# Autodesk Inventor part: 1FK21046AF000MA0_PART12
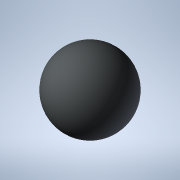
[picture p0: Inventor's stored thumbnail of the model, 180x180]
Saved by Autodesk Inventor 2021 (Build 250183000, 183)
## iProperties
Created: 2025-04
Part Number: 1FK21046AF000MA0_PART12
Material: Generic
Catalog Web Link: www.3dfindit.com
Description: -Servo synchronous motor
Document SubType Name: Modeling
Designer: psAdmin
Mass: 0.137258 g
Surface Area: 1.2868 cm^2
Volume: 0.137258 cm^3
Density: 1 g/cm^3
Appearance: PSOLRGB-212-217-219
Category: PARTsolutions
Title: 1FK21046AF000MA0_PART12
Author: Cadenas PARTsolutions
Comments: Servo synchronous motor
Sending System: PARTsolutions
Preprocessor: ST-DEVELOPER v19.3
PSOL_IDENT_0: {$CADENAS_DATA/23d-libs/siemens_ag/_cat_/1c/1f/1fk21046af000ma0.prj},216 {VTYP=3D},{NB=1FK21046AF000
PSOL_IDENT_1: MA0_PART12},{LINA=1FK21046AF000MA0_PART12},{NN=1FK21046AF000MA0_PART12},{NOPRJ=TRUE},{DATE=19.08.202
PSOL_IDENT_2: 5 14:00:28},{GEOMDATE=30.07.2025 02:02:08},{VERSION=},{LINEID=10},{WBVAR=},{WBNUMERIC=}  {NB=1FK2104
PSOL_IDENT_3: 6AF000MA0_PART12},{LINA=1FK21046AF000MA0_PART12},{KT=DUMMY},{PREVIEW=../../../_pool_/cb/72/p_d211_xx
PSOL_IDENT_4: _00434j.png},{DESCSHORT=SIMOTICS S-1FK2 HD, SINAMICS S210 3AC 400V-480V, 3.2 Nm, 3000 rpm},{DESCLONG=
PSOL_IDENT_5: SIMOTICS S-1FK2 HD servo motor M0=3.2 Nm; PN = 1 kW at nN=3000 rpm (380-480 V); PN = 0.5 kW at nN=15
PSOL_IDENT_6: 00 rpm (200-240 V); degree of protection IP64; cylindrical shaft D19x40mm; absolute encoder 22-bit +
PSOL_IDENT_7: 12-bit multiturn (encoder AM22DQC); with OCC interface; plug size M17, rotatable; SIMOTICS S-1FK2 s
PSOL_IDENT_8: ervomotorfor a wide range of uses in industrial environments. SIMOTICS S‑1FK2 servomotors are compac
PSOL_IDENT_9: t synchronous motors with a high dynamic performance that set themselves apart as a result of their
PSOL_IDENT_10: high power density, degree of protection and overload capability. The motors are available in two va
PSOL_IDENT_11: riants: as High Dynamic variant (highest dynamic performance as a result of the low intrinsic moment
PSOL_IDENT_12: of inertia for applications demanding a high dynamic performance with low moved masses) - and as Co
PSOL_IDENT_13: mpact variant (precise and stable closed-loop control for medium up to large moved masses as a resul
PSOL_IDENT_14: t of a medium intrinsic moment of inertia). SIMOTICSS‑1FK2 servomotors fully exploit their strengths
PSOL_IDENT_15: in a system with the SINAMICSS210 frequency converter and simple connection using the one cable con
PSOL_IDENT_16: nection (OCC). Advantages include the short control and positioning times, fast and precise correcti
PSOL_IDENT_17: on of disturbing quantities as well as stable control with a high dynamic performance. The servo mot
PSOL_IDENT_18: ors can be configured to address a wide range of requirements. For example with and without holding
PSOL_IDENT_19: brake, IP64 or IP65 degree of protection, singleturn or multiturn absolute encoders - to name just a
PSOL_IDENT_20: few. Further, the servomotors are available in different shaft heights extending from 20 to 100. A
PSOL_IDENT_21: shaft sealing ring is available to achieve an IP65 degree of protection and for subsequent mounting
PSOL_IDENT_22: at the motor or as spare part. SIMOTICS - the optimum motor for each and every motion control applic
PSOL_IDENT_23: ation.},{INTNO=195125049666},{SUPPLIERALTNO=1FK2104-6AF00-0MA0},{MANUID=1FK21046AF000MA0},{MANUNAME=
PSOL_IDENT_24: Siemens},{MANUTYPEDESC=Synchronous motor 1FK2-HD 3.2 NM},{AAU732=SIMOTICS},{AAO057=S-1FK2},{AAU734=S
PSOL_IDENT_25: IMOTICS S-1FK2 HD servo motor M0=3.2 Nm; PN = 1 kW at nN=3000 rpm (380-480 V); PN = 0.5 kW at nN=150
PSOL_IDENT_26: 0 rpm (200-240 V); degree of protection IP64; cylindrical shaft D19x40mm; absolute encoder 22-bit +
PSOL_IDENT_27: 12-bit multiturn (encoder AM22DQC); with OCC interface; plug size M17, rotatable;},{AAW338=Synchrono
PSOL_IDENT_28: us motor 1FK2-HD 3.2 NM},{AAO742=SIMOTICS},{AAO663=4042948694374},{NOCUPEROU=1},{PRICEQUANTITY=1},{Q
PSOL_IDENT_29: UANTITYMIN=1},{QUANTITYINT=1},{CTN=85015220},{COO=DE},{AAO676=1FK2104-6AF00-0MA0},{AAO677=Siemens AG
PSOL_IDENT_30: },{ORDERUNIT=C62},{CONTENTUNIT=C62}
NB: 1FK21046AF000MA0_PART12
NT: Servo synchronous motor
NBSYN: $MANUID._PART12
LINA: 1FK21046AF000MA0_PART12
CATALOG: SIEMENS
PREVIEW: ../../../_pool_/cb/72/p_d211_xx_00434j.png
DESCSHORT: SIMOTICS S-1FK2 HD, SINAMICS S210 3AC 400V-480V, 3.2 Nm, 3000 rpm
DESCLONG: SIMOTICS S-1FK2 HD servo motor M0=3.2 Nm; PN = 1 kW at nN=3000 rpm (380-480 V); PN = 0.5 kW at nN=1500 rpm (200-240 V); degree of protection IP64; cylindrical s
INTNO: 195125049666
SUPPLIERALTNO: 1FK2104-6AF00-0MA0
MANUID: 1FK21046AF000MA0
MANUNAME: Siemens
MANUTYPEDESC: Synchronous motor 1FK2-HD 3.2 NM
AAU732: SIMOTICS
AAO057: S-1FK2
AAU734: SIMOTICS S-1FK2 HD servo motor M0=3.2 Nm; PN = 1 kW at nN=3000 rpm (380-480 V); PN = 0.5 kW at nN=1500 rpm (200-240 V); degree of protection IP64; cylindrical s
AAW338: Synchronous motor 1FK2-HD 3.2 NM
AAO742: SIMOTICS
AAO663: 4042948694374.0
NOCUPEROU: 1
PRICEQUANTITY: 1
QUANTITYMIN: 1
QUANTITYINT: 1
CTN: 85015220
COO: DE
ARTICLENO: 1FK21046AF000MA0_PART12
BOMINFO: 1FK21046AF000MA0_PART12
CREATOR: CADENAS GmbH
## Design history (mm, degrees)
feature "2025_04_17_15_39_11_0412"
body "Solid1"
